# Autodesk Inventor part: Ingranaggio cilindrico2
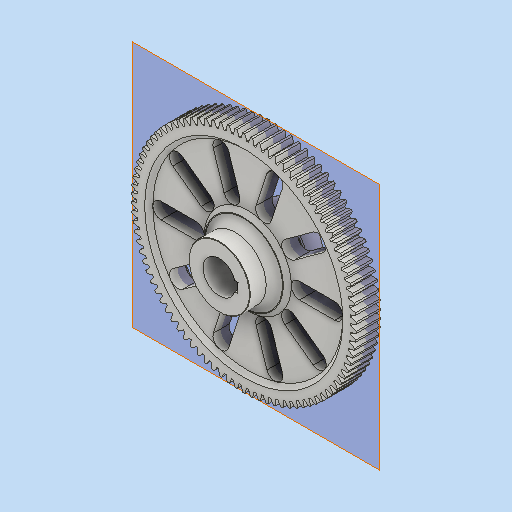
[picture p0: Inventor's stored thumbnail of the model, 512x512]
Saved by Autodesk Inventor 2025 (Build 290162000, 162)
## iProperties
CustomPartVersion: 1
Created: 2026-05
Part Number: Ingranaggio cilindrico2
Material: Acciaio inossidabile
Document SubType Name: Modeling
Designer: R5800u
Categories: <?xml version="1.0" encoding="UTF-16"?> <MemberInstance><Categories><FamilyTemplate><FamilyTemplateParameter ValueType="xs:double" Id="1" ObjectReferenceKey="da
Density: 8 g/cm^3
Appearance: Acciaio
Author: R5800u
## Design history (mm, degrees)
sketch "Sketch1"
  geometry: C1 r 138 at (0, 0)
  constraints: 1 centre point
  dimensions: "d0" = 276 diameter of C1 (= da_da)
extrude "Extrusion1" new body sketch "Sketch1" distance "d1" = 30 (= da_b); taper "d2" = 0 deg
workplane "Work Plane2"
feature "Diametro primitivo" dims "d4" = 10, "d5" = 0
workplane "Work Plane8"
workplane "Work Plane9"
feature "Ingranaggio cilindrico" dims "d68" = 360 deg, "da_b" = 30, "da_d" = 270, "da_aw" = 162, "da_da" = 276, "da_df" = 262.5, "da_dw" = 270, angle "da_beta" = 0 deg, "da_lefttooth" = 0, "da_righttooth" = 0
sketch "Schizzo3"
  geometry: A1 r 131.25 centre (0, 0) between (-48.103, 122.117) and (-50.227, 121.259) reference; 2 further points
  constraints: 1 coincident
hole "Foro1" sketch "Schizzo3" at (0, 0) diameter "d49" = 40; stored, may be unused: countersink angle "d53" = 90 deg, drill point angle "d55" = 118 deg; dims "d50" = 6, "d51" = 4, "d52" = 2, "d54" = 10
sketch "Schizzo4"
  geometry: C1 r 37.5 at (0, 0); C2 r 20 at (0, 0) reference; 1 further point
  constraints: 1 centre point, 1 coincident
  dimensions: "d56" = 75 diameter of C1
extrude "Estrusione2" join sketch "Schizzo4" distance "d57" = 30; taper "d58" = 0 deg
fillet "Raccordo1" dims "d59" = 10
node "Piano di lavoro11"
mirror "Speculare1"
chamfer "Smusso1" distance "d60" = 0.5; stored, may be unused: second distance "d61" = 2, angle "d62" = 45 deg
sketch "Schizzo5"
  geometry: L1 (106.579, 0)-(63.421, 0); L2 (106.579, 10)-(63.421, 10); L3 (63.421, -10)-(106.579, -10); A1 r 10 centre (106.579, 0) between (106.579, -10) and (106.579, 10); A2 r 10 centre (63.421, 0) between (63.421, 10) and (63.421, -10); 2 further points
  constraints: 8 end point, 4 point on circle, 4 tangent, 2 centre point, 1 horizontal, 1 midpoint, 1 parallel
  dimensions: "d63" = 20 diameter of A2; "d64" = 85 distance of point (0, 0) point (85, 0)
extrude "Estrusione3" cut sketch "Schizzo5" extent not by distance; stored distance "d65" = 0; taper "d66" = 0 deg
pattern_circular "Serie circolare1" dims angle "d68" = 360 deg
sketch "Schizzo6"
  geometry: C1 r 37.5 at (0, 0) reference; C2 r 116.579 at (0, 0); C3 r 20 at (0, 0) reference; C4 r 53.421 at (0, 0); A1 r 10 centre (63.421, 0) between (63.421, 10) and (63.421, -10) reference; 1 further point
  constraints: 2 centre point, 2 coincident, 1 tangent
extrude "Estrusione4" cut sketch "Schizzo6" distance "d70" = 5; taper "d71" = 0 deg
mirror "Speculare2"
chamfer "Smusso2" distance "d74" = 5; stored, may be unused: second distance "d75" = 2, angle "d76" = 45 deg
node "Scanalatura4"
body "Solid1"
sketch "Sketch2"
  geometry: C1 r 138 at (0, 0) reference; C2 r 135 at (0, 0)
  constraints: 1 centre point, 1 coincident
  dimensions: "d3" = 270 diameter of C2 (= da_d)
body "Srf1"
feature "Sede chiavetta mozzo"
other parameters: "d16" = 162 (= da_aw), "d17" = 0, "d34" = 2 deg (computed from da_z), "d39" = 0, "d41" = 0, "d43" = 162 (= da_aw), "d46" = 162 (= da_aw), "d47" = 0, "d48" = 0
